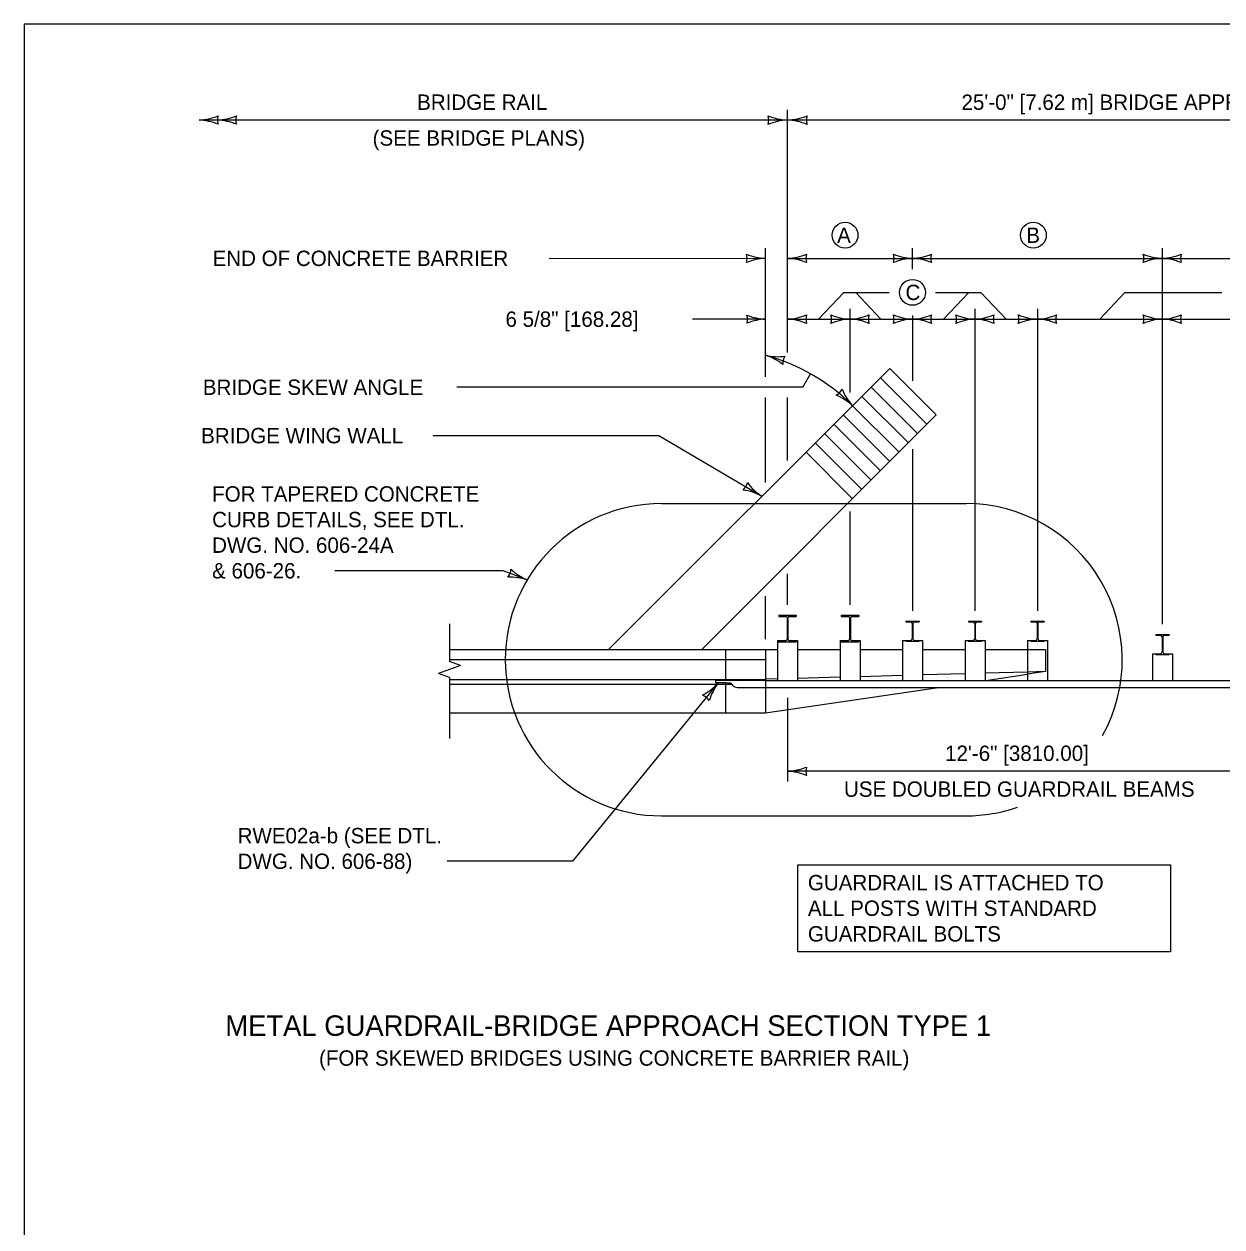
# Model space of a CAD drawing. Extents: x 49991.4 to 50021, y 49987.6 to 50011.4.
# Drawn here: x 50000.336 to 50005.013, y 50006.566 to 50011.263 of the extents above; entities that cross this region are included whole.
import ezdxf

# ---------------------------------------------------------------- set-up
doc = ezdxf.new("R2010")
doc.units = 0
for name, color, linetype in [('Level 1', 7, 'Continuous'), ('Level 2', 7, 'Continuous'), ('Level 3', 7, 'Continuous'), ('Level 4', 7, 'Continuous'), ('Level 6', 7, 'Continuous')]:
    doc.layers.add(name, color=color, linetype=linetype)

msp = doc.modelspace()

# ---------------------------------------------------------------- linework, layer by layer
at = {"layer": 'Level 1'}
for p, q in [((50002.6181, 50008.8203), (50003.7156, 50009.9179)), ((50003.8972, 50009.7363), (50003.7156, 50009.9179)), ((50003.8245, 50009.6637), (50003.6429, 50009.8452)), ((50003.8608, 50009.7), (50003.6792, 50009.8816)), ((50003.7882, 50009.6273), (50003.6066, 50009.8089)), ((50003.7519, 50009.591), (50003.5703, 50009.7726)), ((50002.9813, 50008.8203), (50003.8972, 50009.7363)), ((50003.6792, 50009.5184), (50003.4976, 50009.6999)), ((50003.7156, 50009.5547), (50003.534, 50009.7363)), ((50003.6429, 50009.482), (50003.4613, 50009.6636)), ((50003.6066, 50009.4457), (50003.425, 50009.6273)), ((50003.5703, 50009.4094), (50003.3887, 50009.591)), ((50003.2822, 50008.955), (50003.3508, 50008.955)), ((50003.2822, 50008.955), (50003.2822, 50008.9498)), ((50003.2822, 50008.9498), (50003.3103, 50008.9498)), ((50003.3227, 50008.9498), (50003.3508, 50008.9498)), ((50003.3508, 50008.955), (50003.3508, 50008.9498)), ((50003.5262, 50008.955), (50003.5947, 50008.955)), ((50003.5262, 50008.955), (50003.5262, 50008.9498)), ((50003.5262, 50008.9498), (50003.5543, 50008.9498)), ((50003.5666, 50008.9498), (50003.5947, 50008.9498)), ((50003.5947, 50008.955), (50003.5947, 50008.9498)), ((50003.3149, 50008.9452), (50003.3149, 50008.8607)), ((50003.3181, 50008.9452), (50003.3181, 50008.8607)), ((50003.5588, 50008.9452), (50003.5588, 50008.8607)), ((50003.5621, 50008.9452), (50003.5621, 50008.8607)), ((50003.7788, 50008.9314), (50003.8301, 50008.9314)), ((50003.7788, 50008.9314), (50003.7788, 50008.9286)), ((50003.7788, 50008.9286), (50003.7964, 50008.9286)), ((50003.8033, 50008.9216), (50003.8033, 50008.8631)), ((50003.8055, 50008.9216), (50003.8055, 50008.8631)), ((50003.8125, 50008.9286), (50003.8301, 50008.9286)), ((50003.8301, 50008.9314), (50003.8301, 50008.9286)), ((50004.0228, 50008.9314), (50004.074, 50008.9314)), ((50004.0228, 50008.9314), (50004.0228, 50008.9286)), ((50004.0228, 50008.9286), (50004.0403, 50008.9286)), ((50004.0473, 50008.9216), (50004.0473, 50008.8631)), ((50004.0495, 50008.9216), (50004.0495, 50008.8631)), ((50004.0565, 50008.9286), (50004.074, 50008.9286)), ((50004.074, 50008.9314), (50004.074, 50008.9286)), ((50004.2668, 50008.9314), (50004.3181, 50008.9314)), ((50004.2668, 50008.9314), (50004.2668, 50008.9286)), ((50004.2668, 50008.9286), (50004.2844, 50008.9286)), ((50004.2913, 50008.9216), (50004.2913, 50008.8631)), ((50004.2935, 50008.9216), (50004.2935, 50008.8631)), ((50004.3005, 50008.9286), (50004.3181, 50008.9286)), ((50004.3181, 50008.9314), (50004.3181, 50008.9286)), ((50003.2775, 50008.8561), (50003.2775, 50008.7)), ((50003.2775, 50008.8561), (50003.2816, 50008.8561)), ((50003.2816, 50008.8509), (50003.2816, 50008.8561)), ((50003.2822, 50008.8509), (50003.2822, 50008.8561)), ((50003.2822, 50008.8561), (50003.3103, 50008.8561)), ((50003.3227, 50008.8561), (50003.3508, 50008.8561)), ((50003.3508, 50008.8509), (50003.3508, 50008.8561)), ((50003.3514, 50008.8509), (50003.3514, 50008.8561)), ((50003.3514, 50008.8561), (50003.3555, 50008.8561)), ((50003.3555, 50008.8561), (50003.3555, 50008.7)), ((50003.5214, 50008.8561), (50003.5214, 50008.7)), ((50003.5214, 50008.8561), (50003.5255, 50008.8561)), ((50003.5255, 50008.8509), (50003.5255, 50008.8561)), ((50003.5262, 50008.8509), (50003.5262, 50008.8561)), ((50003.5262, 50008.8561), (50003.5543, 50008.8561)), ((50003.5666, 50008.8561), (50003.5947, 50008.8561)), ((50003.5947, 50008.8509), (50003.5947, 50008.8561)), ((50003.5954, 50008.8509), (50003.5954, 50008.8561)), ((50003.5954, 50008.8561), (50003.5995, 50008.8561)), ((50003.5995, 50008.8561), (50003.5995, 50008.7)), ((50003.7654, 50008.8561), (50003.7654, 50008.7)), ((50003.7654, 50008.8561), (50003.7781, 50008.8561)), ((50003.7781, 50008.8533), (50003.7781, 50008.8561)), ((50003.7781, 50008.8533), (50003.7788, 50008.8533)), ((50003.7788, 50008.8533), (50003.7788, 50008.8561)), ((50003.7788, 50008.8561), (50003.7964, 50008.8561)), ((50003.7788, 50008.8533), (50003.8301, 50008.8533)), ((50003.8125, 50008.8561), (50003.8301, 50008.8561)), ((50003.8301, 50008.8533), (50003.8301, 50008.8561)), ((50003.8307, 50008.8533), (50003.8301, 50008.8533)), ((50003.8307, 50008.8533), (50003.8307, 50008.8561)), ((50003.8307, 50008.8561), (50003.8435, 50008.8561)), ((50003.8435, 50008.8561), (50003.8435, 50008.7)), ((50004.0094, 50008.8561), (50004.0094, 50008.7)), ((50004.0094, 50008.8561), (50004.0221, 50008.8561)), ((50004.0221, 50008.8533), (50004.0221, 50008.8561)), ((50004.0221, 50008.8533), (50004.0228, 50008.8533)), ((50004.0228, 50008.8533), (50004.0228, 50008.8561)), ((50004.0228, 50008.8561), (50004.0403, 50008.8561)), ((50004.0228, 50008.8533), (50004.074, 50008.8533)), ((50004.0565, 50008.8561), (50004.074, 50008.8561)), ((50004.074, 50008.8533), (50004.074, 50008.8561)), ((50004.074, 50008.8533), (50004.0747, 50008.8533)), ((50004.0747, 50008.8533), (50004.0747, 50008.8561)), ((50004.0747, 50008.8561), (50004.0875, 50008.8561)), ((50004.0875, 50008.8561), (50004.0875, 50008.7)), ((50004.2534, 50008.8561), (50004.2534, 50008.7)), ((50004.2534, 50008.8561), (50004.2661, 50008.8561)), ((50004.2661, 50008.8533), (50004.2661, 50008.8561)), ((50004.2661, 50008.8533), (50004.3187, 50008.8533)), ((50004.2668, 50008.8533), (50004.2668, 50008.8561)), ((50004.2668, 50008.8561), (50004.2844, 50008.8561)), ((50004.3005, 50008.8561), (50004.3181, 50008.8561)), ((50004.3181, 50008.8533), (50004.3181, 50008.8561)), ((50004.3187, 50008.8533), (50004.3187, 50008.8561)), ((50004.3187, 50008.8561), (50004.3315, 50008.8561)), ((50004.3315, 50008.8561), (50004.3315, 50008.7)), ((50004.7547, 50008.8793), (50004.806, 50008.8793)), ((50004.7547, 50008.8793), (50004.7547, 50008.8765)), ((50004.7547, 50008.8765), (50004.7723, 50008.8765)), ((50004.7792, 50008.8696), (50004.7792, 50008.811)), ((50004.7815, 50008.8696), (50004.7815, 50008.811)), ((50004.7884, 50008.8765), (50004.806, 50008.8765)), ((50004.806, 50008.8793), (50004.806, 50008.8765)), ((50001.9966, 50008.8203), (50003.0718, 50008.8203)), ((50003.0718, 50008.8203), (50003.2303, 50008.8203)), ((50003.0743, 50008.8203), (50003.0743, 50008.7)), ((50003.2303, 50008.8203), (50003.2303, 50008.5731)), ((50003.2303, 50008.8203), (50003.2775, 50008.8203)), ((50003.2816, 50008.8509), (50003.2822, 50008.8509)), ((50003.2822, 50008.8509), (50003.3508, 50008.8509)), ((50003.3514, 50008.8509), (50003.3508, 50008.8509)), ((50003.3555, 50008.8203), (50003.5214, 50008.8203)), ((50003.5255, 50008.8509), (50003.5262, 50008.8509)), ((50003.5262, 50008.8509), (50003.5947, 50008.8509)), ((50003.5947, 50008.8509), (50003.5954, 50008.8509)), ((50003.5995, 50008.8203), (50003.7654, 50008.8203)), ((50003.8435, 50008.8203), (50004.0094, 50008.8203)), ((50004.0875, 50008.8203), (50004.2534, 50008.8203)), ((50001.9966, 50008.7813), (50003.0718, 50008.7813)), ((50003.0718, 50008.7813), (50003.2303, 50008.7813)), ((50004.7413, 50008.8041), (50004.7413, 50008.7)), ((50004.7413, 50008.8041), (50004.7541, 50008.8041)), ((50004.7541, 50008.8013), (50004.7541, 50008.8041)), ((50004.7541, 50008.8013), (50004.8066, 50008.8013)), ((50004.7547, 50008.8013), (50004.7547, 50008.8041)), ((50004.7547, 50008.8041), (50004.7723, 50008.8041)), ((50004.7884, 50008.8041), (50004.806, 50008.8041)), ((50004.806, 50008.8013), (50004.806, 50008.8041)), ((50004.8066, 50008.8013), (50004.8066, 50008.8041)), ((50004.8066, 50008.8041), (50004.8194, 50008.8041)), ((50004.8194, 50008.8041), (50004.8194, 50008.7)), ((50003.7654, 50008.7189), (50003.5995, 50008.7144)), ((50004.0094, 50008.7257), (50003.8435, 50008.7211)), ((50004.2534, 50008.7324), (50004.0875, 50008.7278)), ((50004.0906, 50008.7), (50004.2534, 50008.724)), ((50001.9966, 50008.7033), (50003.0719, 50008.7033)), ((50001.9966, 50008.6847), (50003.0998, 50008.6847)), ((50003.0353, 50008.7), (50003.0353, 50008.6905)), ((50003.2303, 50008.7), (50003.0353, 50008.7)), ((50003.0697, 50008.6905), (50003.0353, 50008.6905)), ((50003.0718, 50008.7032), (50003.2303, 50008.7032)), ((50003.0743, 50008.6902), (50003.0743, 50008.5731)), ((50007.5069, 50008.6714), (50003.1301, 50008.6714)), ((50003.2775, 50008.7055), (50003.2303, 50008.7042)), ((50003.2303, 50008.7), (50007.5069, 50008.7)), ((50003.2303, 50008.5731), (50003.8972, 50008.6714)), ((50003.5214, 50008.7122), (50003.3555, 50008.7077)), ((50001.9966, 50008.5731), (50003.0718, 50008.5731)), ((50003.0718, 50008.5731), (50003.2303, 50008.5731))]:
    msp.add_line(p, q, dxfattribs=at)
msp.add_lwpolyline([(50008.6146, 50011.2628), (50000.3356, 50011.2628), (50000.3356, 50000.0624), (50008.6146, 50000.0624)], close=True, dxfattribs=at)
for centre, radius, start, end in [((50003.3103, 50008.9452), 0.00455, 0, 90), ((50003.3227, 50008.9452), 0.00455, 90, 180), ((50003.5543, 50008.9452), 0.00455, 0, 90), ((50003.5666, 50008.9452), 0.00455, 90, 180), ((50003.7964, 50008.9216), 0.00696, 0, 90), ((50003.8125, 50008.9216), 0.00696, 90, 180), ((50004.0403, 50008.9216), 0.00696, 0, 90), ((50004.0565, 50008.9216), 0.00696, 90, 180), ((50004.2844, 50008.9216), 0.00696, 0, 90), ((50004.3005, 50008.9216), 0.00696, 90, 180), ((50003.3103, 50008.8607), 0.00455, 270, 0), ((50003.3227, 50008.8607), 0.00455, 180, 270), ((50003.5543, 50008.8607), 0.00455, 270, 0), ((50003.5666, 50008.8607), 0.00455, 180, 270), ((50003.7964, 50008.8631), 0.00696, 270, 0), ((50003.8125, 50008.8631), 0.00696, 180, 270), ((50004.0403, 50008.8631), 0.00696, 270, 0), ((50004.0565, 50008.8631), 0.00696, 180, 270), ((50004.2844, 50008.8631), 0.00696, 270, 0), ((50004.3005, 50008.8631), 0.00696, 180, 270), ((50004.7723, 50008.8696), 0.00696, 0, 90), ((50004.7884, 50008.8696), 0.00696, 90, 180), ((50004.7723, 50008.811), 0.00696, 270, 0), ((50004.7884, 50008.811), 0.00696, 180, 270)]:
    msp.add_arc(centre, radius, start, end, dxfattribs=at)
msp.add_spline([(50003.1301, 50008.6715), (50003.1212, 50008.6714), (50003.112, 50008.6733), (50003.1059, 50008.6774), (50003.1009, 50008.6834), (50003.097, 50008.6874), (50003.0878, 50008.6894), (50003.0697, 50008.6905)], degree=3, dxfattribs=at)
at = {"layer": 'Level 2'}
msp.add_lwpolyline([(50003.3561, 50007.98), (50004.8112, 50007.98), (50004.8112, 50007.64), (50003.3561, 50007.64)], close=True, dxfattribs=at)
for centre, radius in [((50003.5412, 50010.4383), 0.0504), ((50004.2763, 50010.4383), 0.0504), ((50003.8042, 50010.215), 0.0505)]:
    msp.add_circle(centre, radius, dxfattribs=at)
at = {"layer": 'Level 3'}
for p, q in [((50003.3165, 50009.9804), (50003.3165, 50010.9278)), ((50003.3165, 50010.8878), (50001.0189, 50010.8878)), ((50007.2181, 50010.8878), (50003.3165, 50010.8878)), ((50003.2303, 50009.8848), (50003.2303, 50010.3879)), ((50003.8042, 50010.3054), (50003.8042, 50010.3879)), ((50004.7796, 50010.3878), (50004.7796, 50008.9193)), ((50002.3862, 50010.348), (50003.2303, 50010.3479)), ((50003.3165, 50010.3479), (50003.8042, 50010.3479)), ((50003.8042, 50010.3479), (50004.7796, 50010.3479)), ((50004.7796, 50010.3479), (50007.2181, 50010.3479)), ((50003.5358, 50010.215), (50003.4376, 50010.1105)), ((50003.5358, 50010.215), (50003.7137, 50010.215)), ((50003.5831, 50010.215), (50003.6813, 50010.1105)), ((50003.8946, 50010.215), (50004.0714, 50010.215)), ((50004.0241, 50010.215), (50003.9259, 50010.1105)), ((50004.0714, 50010.215), (50004.1695, 50010.1105)), ((50004.6338, 50010.215), (50004.5357, 50010.1105)), ((50004.6338, 50010.215), (50005.0126, 50010.215)), ((50003.5603, 50010.1505), (50003.5603, 50009.8241)), ((50003.8042, 50010.1245), (50003.8042, 50009.8693)), ((50004.048, 50010.1505), (50004.048, 50008.9714)), ((50004.2919, 50010.1505), (50004.2919, 50008.9714)), ((50003.2303, 50010.1105), (50002.9451, 50010.1105)), ((50003.3165, 50010.1105), (50003.5603, 50010.1105)), ((50003.5603, 50010.1105), (50003.8042, 50010.1105)), ((50003.8042, 50010.1105), (50004.048, 50010.1105)), ((50004.048, 50010.1105), (50004.2919, 50010.1105)), ((50004.2919, 50010.1105), (50004.7796, 50010.1105)), ((50004.7796, 50010.1105), (50005.2672, 50010.1105)), ((50003.376, 50009.8448), (50003.4057, 50009.8974)), ((50003.376, 50009.8448), (50002.0257, 50009.8448)), ((50003.2303, 50009.4726), (50003.2303, 50009.8048)), ((50003.3165, 50009.5588), (50003.3165, 50009.8048)), ((50001.9329, 50009.6557), (50002.8135, 50009.6557)), ((50002.8135, 50009.6557), (50003.2168, 50009.4191)), ((50003.8042, 50009.6033), (50003.8042, 50008.9714)), ((50003.5603, 50009.3594), (50003.5603, 50008.995)), ((50002.2058, 50009.128), (50001.5485, 50009.128)), ((50002.3002, 50009.0923), (50002.2058, 50009.128)), ((50003.3165, 50008.995), (50003.3165, 50009.1156)), ((50003.2303, 50008.8603), (50003.2303, 50009.0294)), ((50003.0461, 50008.6904), (50002.4772, 50007.9936)), ((50003.3165, 50008.6315), (50003.3165, 50008.3052)), ((50005.2673, 50008.3452), (50003.3165, 50008.3452)), ((50002.4772, 50007.9936), (50001.9878, 50007.9936))]:
    msp.add_line(p, q, dxfattribs=at)
for centre, radius, start, end in [((50001.0077, 50011.1148), 0.2273, 272.8273, 292.0772), ((50001.01, 50010.6711), 0.2168, 67.456, 87.6395), ((50001.144, 50010.8878), 0.0534, 162.1388, 197.8612), ((50001.0793, 50011.1148), 0.2273, 272.8273, 292.0772), ((50001.0816, 50010.6711), 0.2168, 67.456, 87.6395), ((50001.2156, 50010.8878), 0.0534, 162.1388, 197.8612), ((50003.3256, 50011.1099), 0.2223, 247.456, 267.6395), ((50003.1883, 50010.8878), 0.0548, 342.1388, 17.8612), ((50003.328, 50010.655), 0.233, 92.8273, 112.0772), ((50003.305, 50011.1205), 0.233, 272.8273, 292.0772), ((50003.3073, 50010.6656), 0.2223, 67.456, 87.6395), ((50003.4447, 50010.8878), 0.0548, 162.1388, 197.8612), ((50003.2393, 50010.5645), 0.2168, 247.456, 267.6395), ((50003.1053, 50010.3479), 0.0534, 342.1388, 17.8612), ((50003.3053, 50010.5748), 0.2273, 272.8273, 292.0772), ((50003.4415, 50010.3479), 0.0534, 162.1388, 197.8612), ((50003.8131, 50010.5645), 0.2168, 247.456, 267.6395), ((50003.6791, 50010.3479), 0.0534, 342.1388, 17.8612), ((50003.793, 50010.5748), 0.2273, 272.8273, 292.0772), ((50003.9292, 50010.3479), 0.0534, 162.1388, 197.8612), ((50004.7885, 50010.5645), 0.2168, 247.456, 267.6395), ((50004.6545, 50010.3479), 0.0534, 342.1388, 17.8612), ((50004.7684, 50010.5748), 0.2273, 272.8273, 292.0772), ((50004.9046, 50010.3479), 0.0534, 162.1388, 197.8612), ((50003.2415, 50010.1209), 0.2273, 92.8273, 112.0772), ((50003.3076, 50010.1312), 0.2168, 67.456, 87.6395), ((50003.8154, 50010.1209), 0.2273, 92.8273, 112.0772), ((50003.7952, 50010.1312), 0.2168, 67.456, 87.6395), ((50004.7908, 50010.1209), 0.2273, 92.8273, 112.0772), ((50004.7706, 50010.1312), 0.2168, 67.456, 87.6395), ((50003.239, 50010.3216), 0.2113, 247.456, 267.6395), ((50003.1085, 50010.1105), 0.0521, 342.1388, 17.8612), ((50003.3053, 50010.3375), 0.2273, 272.8273, 292.0772), ((50003.4415, 50010.1105), 0.0534, 162.1388, 197.8612), ((50003.5693, 50010.3272), 0.2168, 247.456, 267.6395), ((50003.4353, 50010.1105), 0.0534, 342.1388, 17.8612), ((50003.5491, 50010.3375), 0.2273, 272.8273, 292.0772), ((50003.6854, 50010.1105), 0.0534, 162.1388, 197.8612), ((50003.8131, 50010.3272), 0.2168, 247.456, 267.6395), ((50003.6791, 50010.1105), 0.0534, 342.1388, 17.8612), ((50003.793, 50010.3375), 0.2273, 272.8273, 292.0772), ((50003.9292, 50010.1105), 0.0534, 162.1388, 197.8612), ((50004.057, 50010.3272), 0.2168, 247.456, 267.6395), ((50003.923, 50010.1105), 0.0534, 342.1388, 17.8612), ((50004.0368, 50010.3375), 0.2273, 272.8273, 292.0772), ((50004.1731, 50010.1105), 0.0534, 162.1388, 197.8612), ((50004.3008, 50010.3272), 0.2168, 247.456, 267.6395), ((50004.1668, 50010.1105), 0.0534, 342.1388, 17.8612), ((50004.2807, 50010.3375), 0.2273, 272.8273, 292.0772), ((50004.4169, 50010.1105), 0.0534, 162.1388, 197.8612), ((50004.7885, 50010.3272), 0.2168, 247.456, 267.6395), ((50004.6545, 50010.1105), 0.0534, 342.1388, 17.8612), ((50004.7683, 50010.3375), 0.2273, 272.8273, 292.0772), ((50004.9046, 50010.1105), 0.0534, 162.1388, 197.8612), ((50003.2413, 50009.8894), 0.2214, 92.8273, 112.0772), ((50003.3076, 50009.8939), 0.2168, 67.456, 87.6395), ((50003.5715, 50009.8835), 0.2273, 92.8273, 112.0772), ((50003.5514, 50009.8939), 0.2168, 67.456, 87.6395), ((50003.8154, 50009.8835), 0.2273, 92.8273, 112.0772), ((50003.7952, 50009.8939), 0.2168, 67.456, 87.6395), ((50004.0592, 50009.8835), 0.2273, 92.8273, 112.0772), ((50004.0391, 50009.8939), 0.2168, 67.456, 87.6395), ((50004.3031, 50009.8835), 0.2273, 92.8273, 112.0772), ((50004.2829, 50009.8939), 0.2168, 67.456, 87.6395), ((50004.7908, 50009.8835), 0.2273, 92.8273, 112.0772), ((50004.7706, 50009.8939), 0.2168, 67.456, 87.6395), ((50003.0289, 50009.2294), 0.767, 45.0947, 74.7701), ((50003.1648, 50009.7627), 0.2168, 52.2261, 72.4096), ((50003.2791, 50010.1913), 0.2273, 257.5974, 276.8473), ((50003.351, 50009.9365), 0.0534, 146.9089, 182.6313), ((50003.4817, 50009.8609), 0.0534, 297.2335, 332.9559), ((50003.418, 50009.6039), 0.2273, 47.922, 67.1718), ((50003.7296, 50009.9197), 0.2168, 202.5507, 222.7342), ((50003.1062, 50009.484), 0.0548, 311.7363, 347.4587), ((50003.3371, 50009.606), 0.2223, 217.0535, 237.237), ((50003.109, 50009.2126), 0.233, 62.4248, 81.6747), ((50002.1833, 50009.1366), 0.0534, 321.396, 357.1183), ((50002.2303, 50008.8762), 0.2271, 72.0845, 91.3343), ((50002.3852, 50009.2916), 0.2167, 226.7132, 246.8967), ((50002.8798, 50008.838), 0.2223, 298.2282, 318.4117), ((50003.2336, 50008.5522), 0.233, 143.5995, 162.8494), ((50002.965, 50008.5911), 0.0548, 32.911, 68.6334), ((50003.3053, 50008.5722), 0.2273, 272.8273, 292.0772), ((50003.3076, 50008.1286), 0.2168, 67.456, 87.6395), ((50003.4416, 50008.3452), 0.0534, 162.1388, 197.8612)]:
    msp.add_arc(centre, radius, start, end, dxfattribs=at)
at = {"layer": 'Level 4'}
for p, q in [((50002.8241, 50009.3902), (50004.0137, 50009.3902)), ((50004.2534, 50008.8203), (50004.3233, 50008.8203)), ((50004.3233, 50008.8203), (50004.3233, 50008.7343)), ((50004.3233, 50008.7343), (50004.2534, 50008.724)), ((50004.3233, 50008.7343), (50004.2534, 50008.7324)), ((50002.8241, 50008.171), (50004.0137, 50008.171))]:
    msp.add_line(p, q, dxfattribs=at)
for centre, start, end in [((50002.8241, 50008.7807), 90, 270), ((50004.0136, 50008.7806), 331.0164, 90), ((50004.0136, 50008.7806), 270, 289.2909)]:
    msp.add_arc(centre, 0.6096, start, end, dxfattribs=at)
at = {"layer": 'Level 6'}
for p, q in [((50001.9966, 50008.9204), (50001.9966, 50008.7731)), ((50002.04, 50008.7577), (50001.9966, 50008.7731)), ((50001.9966, 50008.7424), (50001.9534, 50008.7269)), ((50001.9966, 50008.7116), (50001.9534, 50008.7269)), ((50002.04, 50008.7577), (50001.9966, 50008.7424)), ((50001.9966, 50008.7116), (50001.9966, 50008.4731))]:
    msp.add_line(p, q, dxfattribs=at)

# ---------------------------------------------------------------- texts
at = {"layer": 'Level 2'}
for s, height, p in [('BRIDGE RAIL', 0.06, (50001.8703, 50010.9278)), ('25\'-0" [7.62 m] BRIDGE APPROACH SECTION PAY LIMITS', 0.06, (50003.9957, 50010.9278)), ('(SEE BRIDGE PLANS)', 0.06, (50001.6965, 50010.7878)), ('A', 0.06, (50003.5102, 50010.4083)), ('B', 0.06, (50004.2486, 50010.4083)), ('END OF CONCRETE BARRIER', 0.06, (50001.0716, 50010.318)), ('C', 0.06, (50003.7771, 50010.185)), ('6 5/8" [168.28]', 0.06, (50002.2153, 50010.0805)), ('BRIDGE SKEW ANGLE', 0.06, (50001.0336, 50009.8148)), ('BRIDGE WING WALL', 0.06, (50001.027, 50009.6257)), ('FOR TAPERED CONCRETE ', 0.06, (50001.0698, 50009.398)), ('CURB DETAILS, SEE DTL. ', 0.06, (50001.0698, 50009.298)), ('DWG. NO. 606-24A ', 0.06, (50001.0698, 50009.198)), ('& 606-26.', 0.06, (50001.0698, 50009.098)), ('12\'-6" [3810.00]', 0.06, (50003.9317, 50008.3853)), ('USE DOUBLED GUARDRAIL BEAMS', 0.06, (50003.5369, 50008.2453)), ('RWE02a-b (SEE DTL.', 0.06, (50001.1693, 50008.0636)), ('DWG. NO. 606-88)', 0.06, (50001.1693, 50007.9636)), ('GUARDRAIL IS ATTACHED TO ', 0.06, (50003.3961, 50007.8802)), ('ALL POSTS WITH STANDARD', 0.06, (50003.3961, 50007.7802)), ('GUARDRAIL BOLTS', 0.06, (50003.3961, 50007.6802)), ('METAL GUARDRAIL-BRIDGE APPROACH SECTION TYPE 1', 0.08, (50001.1213, 50007.3119)), ('(FOR SKEWED BRIDGES USING CONCRETE BARRIER RAIL)', 0.06, (50001.4873, 50007.1952))]:
    msp.add_text(s, height=height, dxfattribs=at).set_placement(p)

doc.saveas('drawing.dxf')
